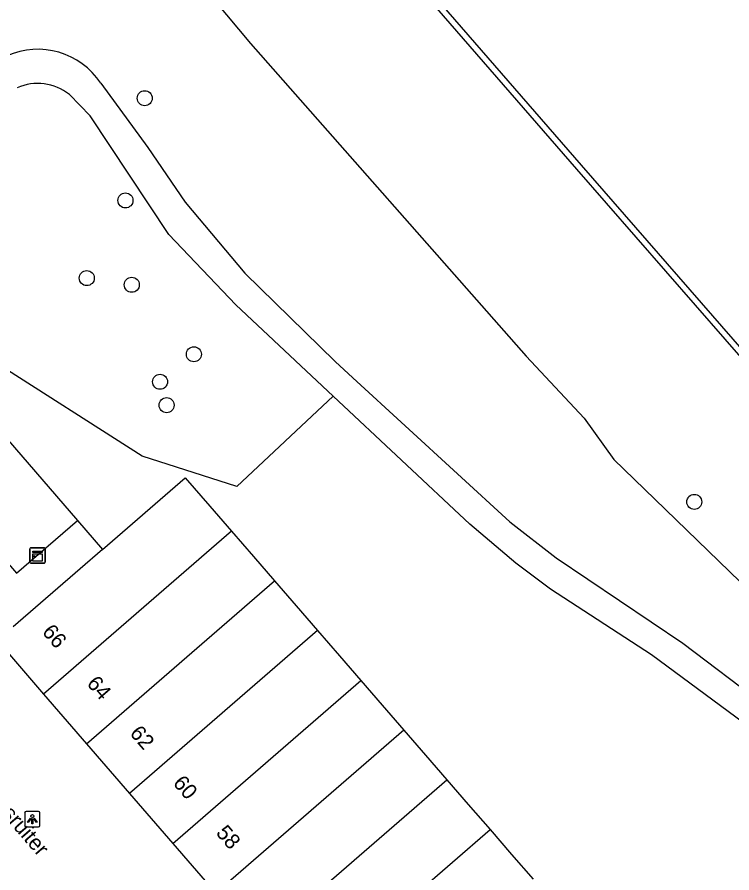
# Model space of a CAD drawing. Extents: x 156664 to 157568, y 383571 to 384421.
# Drawn here: x 156925.9 to 156972.4, y 384254.3 to 384310 of the extents above; entities that cross this region are included whole.
import ezdxf

# ---------------------------------------------------------------- set-up
doc = ezdxf.new("R2010")
doc.units = 0
for name, color, linetype in [('IMGEO_Boom', 7, 'Continuous'), ('IMGEO_Kademuur', 7, 'Continuous'), ('IMGEO_Kast', 7, 'Continuous'), ('IMGEO_Lichtpunt', 7, 'Continuous'), ('IMGEO_Loofbos', 7, 'Continuous'), ('IMGEO_Openbare_ruimte_label', 7, 'Continuous'), ('IMGEO_Pand', 7, 'Continuous'), ('IMGEO_Pand_nummerreeks', 7, 'Continuous'), ('IMGEO_Voetpad_gesloten', 7, 'Continuous'), ('IMGEO_Voetpad_halfverhard', 7, 'Continuous'), ('IMGEO_Voetpad_open', 7, 'Continuous')]:
    doc.layers.add(name, color=color, linetype=linetype)

msp = doc.modelspace()

# ---------------------------------------------------------------- linework, layer by layer
at = {"layer": 'IMGEO_Boom'}
for centre in [(156934.194, 384304.724), (156932.938, 384298.073), (156930.423, 384293.02), (156933.35, 384292.584), (156937.391, 384288.061), (156935.191, 384286.274), (156935.618, 384284.752), (156969.958, 384278.459)]:
    msp.add_circle(centre, 0.489, dxfattribs=at)
at = {"layer": 'IMGEO_Kademuur'}
for points in [[(156926.889, 384340.699), (156925.562, 384342.268), (156926.015, 384342.626), (156939.023, 384327.504), (156962.601, 384300.361), (156983.822, 384276.032), (156992.333, 384266.337), (156993.035, 384263.602), (157006.311, 384248.534), (157023.845, 384228.315), (157027.035, 384224.694), (157026.735, 384224.429), (157025.556, 384225.768)], [(156928.32, 384339.009), (156928.694, 384338.918), (156938.721, 384327.243), (156962.299, 384300.099), (156983.521, 384275.769), (156991.97, 384266.145), (156992.672, 384263.41), (157006.01, 384248.271), (157023.543, 384228.051), (157023.763, 384227.802)]]:
    msp.add_lwpolyline(points, dxfattribs=at)
at = {"layer": 'IMGEO_Kast'}
for p, q in [((156926.718, 384274.545), (156926.718, 384275.386)), ((156926.718, 384275.386), (156926.718, 384274.545)), ((156926.793, 384275.47), (156927.634, 384275.47)), ((156927.634, 384275.47), (156926.793, 384275.47)), ((156927.718, 384275.395), (156927.718, 384274.554)), ((156927.718, 384274.554), (156927.718, 384275.395)), ((156927.643, 384274.47), (156926.802, 384274.47)), ((156926.802, 384274.47), (156927.643, 384274.47))]:
    msp.add_line(p, q, dxfattribs=at)
for points in [[(156926.913, 384275.26), (156927.513, 384275.26), (156927.513, 384275.175), (156926.913, 384275.175), (156926.913, 384275.26)], [(156926.913, 384275.085), (156927.513, 384275.085), (156927.513, 384274.596), (156926.913, 384274.596), (156926.913, 384275.085)]]:
    msp.add_lwpolyline(points, dxfattribs=at)
msp.add_circle((156926.997, 384274.934), 0.0377, dxfattribs=at)
for centre, start, end in [((156926.796, 384275.392), 92.4484, 184.2845), ((156926.796, 384275.392), 92.4484, 184.2845), ((156927.64, 384275.392), 2.4484, 94.2845), ((156927.64, 384275.392), 2.4484, 94.2845), ((156926.796, 384274.548), 182.4484, 274.2845), ((156926.796, 384274.548), 182.4484, 274.2845), ((156927.64, 384274.548), 272.4484, 4.2845), ((156927.64, 384274.548), 272.4484, 4.2845)]:
    msp.add_arc(centre, 0.0779, start, end, dxfattribs=at)
at = {"layer": 'IMGEO_Lichtpunt'}
for p, q in [((156927.282, 384258.313), (156926.474, 384258.313)), ((156927.282, 384258.313), (156926.474, 384258.313)), ((156926.38, 384258.218), (156926.38, 384257.411)), ((156926.38, 384258.218), (156926.38, 384257.411)), ((156927.376, 384257.411), (156927.376, 384258.218)), ((156927.376, 384257.411), (156927.376, 384258.218)), ((156926.474, 384257.317), (156927.282, 384257.317)), ((156926.474, 384257.317), (156927.282, 384257.317))]:
    msp.add_line(p, q, dxfattribs=at)
for points in [[(156926.754, 384257.882), (156926.793, 384257.854), (156926.605, 384257.592), (156926.567, 384257.619), (156926.754, 384257.882)], [(156926.856, 384257.834), (156926.903, 384257.834), (156926.903, 384257.512), (156926.856, 384257.512), (156926.856, 384257.834)], [(156926.966, 384257.854), (156927.004, 384257.881), (156927.191, 384257.619), (156927.152, 384257.591), (156926.966, 384257.854)]]:
    msp.add_lwpolyline(points, dxfattribs=at)
msp.add_circle((156926.879, 384258.016), 0.0994, dxfattribs=at)
for centre, start, end in [((156926.474, 384258.218), 90, 180), ((156926.474, 384258.218), 90, 180), ((156927.282, 384258.218), 0, 90), ((156927.282, 384258.218), 0, 90), ((156926.474, 384257.411), 180, 270), ((156926.474, 384257.411), 180, 270), ((156927.282, 384257.411), 270, 0), ((156927.282, 384257.411), 270, 360)]:
    msp.add_arc(centre, 0.0946, start, end, dxfattribs=at)
at = {"layer": 'IMGEO_Loofbos'}
for points in [[(156933.486, 384317.366), (156941.083, 384308.281), (156959.022, 384287.93), (156962.788, 384283.898), (156964.732, 384281.224), (156967.395, 384278.643), (156975.024, 384271.247), (156978.622, 384265.56)], [(156946.464, 384285.343), (156940.187, 384279.465), (156934.032, 384281.434), (156924.213, 384287.669), (156921.611, 384292.197)]]:
    msp.add_lwpolyline(points, dxfattribs=at)
at = {"layer": 'IMGEO_Pand'}
for points in [[(156931.448, 384275.362), (156936.831, 384280.021), (156938.435, 384278.17), (156939.841, 384276.547)], [(156939.841, 384276.547), (156927.603, 384265.957)], [(156939.841, 384276.547), (156941.265, 384274.904), (156942.642, 384273.315)], [(156931.448, 384275.362), (156925.642, 384270.338)], [(156930.409, 384262.715), (156942.642, 384273.315)], [(156942.642, 384273.315), (156944.041, 384271.7), (156945.442, 384270.083)], [(156945.442, 384270.083), (156933.209, 384259.481)], [(156945.442, 384270.083), (156946.871, 384268.435), (156948.256, 384266.836)], [(156924.671, 384269.498), (156924.595, 384269.432), (156927.603, 384265.957)], [(156936.014, 384256.239), (156948.256, 384266.836)], [(156948.256, 384266.836), (156949.642, 384265.236), (156951.063, 384263.597)], [(156927.603, 384265.957), (156930.409, 384262.715)], [(156951.063, 384263.597), (156938.813, 384253.005)], [(156951.063, 384263.597), (156952.468, 384261.976), (156953.864, 384260.365)], [(156930.409, 384262.715), (156933.209, 384259.481)], [(156941.619, 384249.764), (156953.864, 384260.365)], [(156953.864, 384260.365), (156955.252, 384258.763), (156956.664, 384257.133)], [(156933.209, 384259.481), (156936.014, 384256.239)], [(156944.424, 384246.522), (156956.664, 384257.133)], [(156956.664, 384257.133), (156958.073, 384255.507), (156959.465, 384253.901)], [(156936.014, 384256.239), (156938.813, 384253.005)]]:
    msp.add_lwpolyline(points, dxfattribs=at)
at = {"layer": 'IMGEO_Voetpad_gesloten'}
for points in [[(156918.639, 384286.952), (156920.225, 384288.334), (156929.811, 384277.257)], [(156916.278, 384284.895), (156925.856, 384273.817), (156929.811, 384277.257)]]:
    msp.add_lwpolyline(points, dxfattribs=at)
at = {"layer": 'IMGEO_Voetpad_halfverhard'}
for points in [[(156931.33, 384305.695), (156934.402, 384301.517), (156936.828, 384297.951), (156940.712, 384293.341), (156946.593, 384287.588), (156947.738, 384286.536), (156957.949, 384277.16), (156960.969, 384274.816), (156969.206, 384269.258), (156974.485, 384265.285), (156978.508, 384262.205)], [(156946.464, 384285.343), (156940.124, 384291.277), (156935.757, 384295.859), (156930.652, 384303.568), (156929.29, 384304.956)], [(156977.53, 384260.641), (156973.154, 384264.094), (156967.174, 384268.505), (156960.609, 384272.783), (156958.347, 384274.467), (156955.359, 384277.019), (156946.464, 384285.343)]]:
    msp.add_lwpolyline(points, dxfattribs=at)
for centre, radius, start, end in [((156927.233, 384303.004), 4.902, 33.2943, 114.2061), ((156927.225, 384302.38), 3.302, 51.283, 113.8787)]:
    msp.add_arc(centre, radius, start, end, dxfattribs=at)
at = {"layer": 'IMGEO_Voetpad_open'}
msp.add_lwpolyline([(156929.811, 384277.257), (156931.448, 384275.362)], dxfattribs=at)

# ---------------------------------------------------------------- texts
at = {"layer": 'IMGEO_Openbare_ruimte_label'}
msp.add_text('Bosruiter', height=1, rotation=310.8624, dxfattribs=at).set_placement((156923.795, 384259.374))
at = {"layer": 'IMGEO_Pand_nummerreeks'}
for s, p in [('66', (156927.466, 384269.966)), ('64', (156930.373, 384266.607)), ('62', (156933.171, 384263.374)), ('60', (156935.98, 384260.129)), ('58', (156938.782, 384256.891))]:
    msp.add_text(s, height=1, rotation=310.8765, dxfattribs=at).set_placement(p)

doc.saveas('drawing.dxf')
